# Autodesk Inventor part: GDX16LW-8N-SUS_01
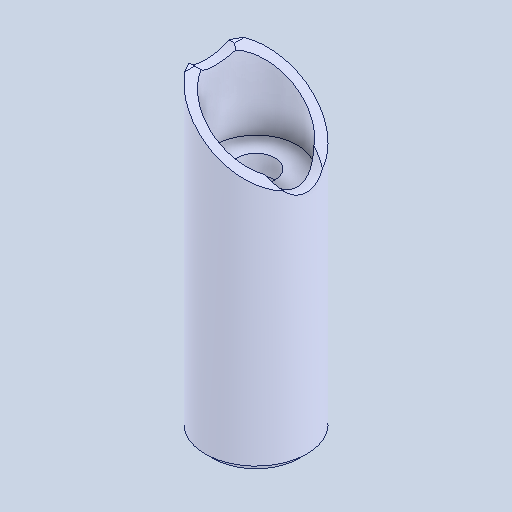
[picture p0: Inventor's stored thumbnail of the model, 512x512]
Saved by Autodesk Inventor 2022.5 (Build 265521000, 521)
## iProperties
Created: 2024-06
Part Number: GDX16LW-8N-SUS_01
Material: 一般
Document SubType Name: Modeling
Designer: ImaoCorp
Density: 1 g/cm^3
Appearance: 既定
Author: ImaoCorp
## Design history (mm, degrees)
feature "GDX16LW-8N-SUS_01"
node "ソリッド1"
